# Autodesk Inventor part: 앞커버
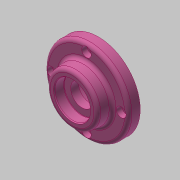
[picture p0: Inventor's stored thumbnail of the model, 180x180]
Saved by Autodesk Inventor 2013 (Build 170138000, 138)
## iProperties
Created: 2017-08
Part Number: 앞커버
Material: 알루미늄 6061
Document SubType Name: Modeling
Designer: mduedu
Density: 2.71 g/cm^3
Mass: 117.254 g
Surface Area: 148.119 cm^2
Volume: 43.2673 cm^3
Author: mduedu
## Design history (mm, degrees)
sketch "스케치1"
  geometry: C1 r 35 at (0, 0); 1 further point
  constraints: 1 centre point, 1 coincident
  dimensions: "d0" = 70 diameter of C1
extrude "돌출1" new body sketch "스케치1" distance "d1" = 10; taper "d2" = 0 deg
sketch "스케치2"
  geometry: C1 r 22 at (0, 0); 1 further point
  constraints: 1 centre point, 1 coincident
  dimensions: "d3" = 44 diameter of C1
node "작업 평면1"
sketch "스케치3"
  geometry: C1 r 21 at (0, 0); 1 further point
  constraints: 1 centre point, 1 coincident
  dimensions: "d5" = 42 diameter of C1
feature "로프트1" sketch "스케치3" dims "d6" = 0, "d7" = 90 deg, "d8" = 0, "d9" = 90 deg
sketch "스케치4"
  geometry: C1 r 24 at (0, 0); 1 further point
  constraints: 1 centre point, 1 coincident
  dimensions: "d86" = 48 diameter of C1
extrude "돌출2" join sketch "스케치4" distance "d10" = 8; taper "d11" = 0 deg
hole "구멍1" diameter "d14" = 40; stored, may be unused: countersink angle "d18" = 90 deg, drill point angle "d20" = 0 deg; dims "d15" = 6, "d16" = 4, "d17" = 2, "d19" = 12, "d87" = 10, "d88" = 10
hole "구멍2" diameter "d23" = 34; stored, may be unused: countersink angle "d27" = 90 deg, drill point angle "d29" = 0 deg; dims "d21" = 10, "d22" = 10, "d24" = 6, "d25" = 4, "d26" = 2, "d28" = 3
hole "구멍3" diameter "d32" = 19; stored, may be unused: countersink angle "d36" = 90 deg, drill point angle "d38" = 0 deg; dims "d30" = 10, "d31" = 10, "d33" = 6, "d34" = 4, "d35" = 2, "d37" = 3
chamfer "모따기1" distance "d39" = 1; stored, may be unused: second distance "d40" = 2, angle "d41" = 45 deg
sketch "스케치5"
  geometry: C1 r 15 at (0, 0); 1 further point
  constraints: 1 centre point, 1 coincident
  dimensions: "d42" = 30 diameter of C1
extrude "돌출3" cut sketch "스케치5" distance "d43" = 8.3; taper "d44" = 0 deg
chamfer "모따기2" distance "d47" = 0.8; stored, may be unused: second distance "d48" = 2, angle "d49" = 30 deg
fillet "모깎기1" dims "d50" = 0.3
fillet "모깎기2" dims "d51" = 0.3
fillet "모깎기3" dims "d52" = 3
sketch "스케치6" dims "d53" = 58
  geometry: 6 further points
  constraints: 2 vertical alignment, 1 coincident, 7 other
  dimensions: "d56" = 360 deg dimension on point (0, 0) point (0, 29) (derived)
sketch "스케치9" dims "d85" = 58 (derived)
  geometry: 6 further points
  constraints: 1 coincident, 1 vertical alignment, 6 other
hole "구멍6" sketch "스케치9" at (-29, 0), (0, -29), (29, 0), (0, 29) diameter "d72" = 4.5; stored, may be unused: countersink angle "d76" = 90 deg, drill point angle "d78" = 0 deg; dims "d73" = 6, "d74" = 8, "d75" = 4.6, "d77" = 8
fillet "모깎기4" dims "d79" = 3
fillet "모깎기5" dims "d80" = 3
fillet "모깎기6" dims "d81" = 3
node "솔리드1"
other parameters: "d4" = 12
